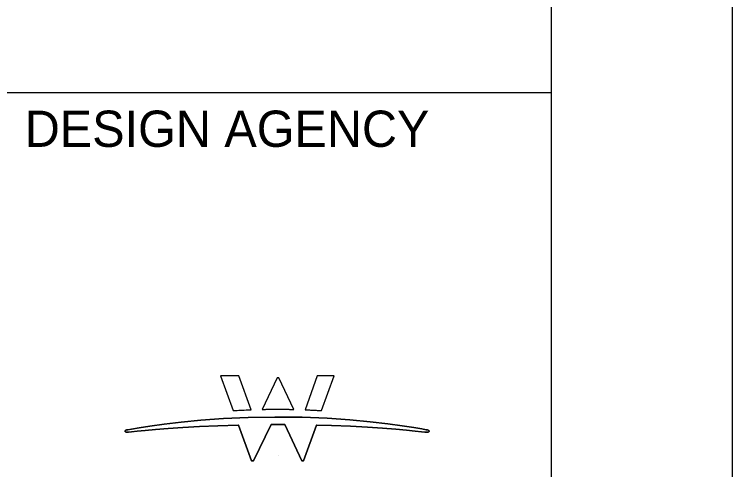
# Model space of a CAD drawing. Extents: x 0 to 34, y 0 to 22.
# Drawn here: x 32.021 to 34, y 3.46 to 4.716 of the extents above; entities that cross this region are included whole.
import ezdxf

# ---------------------------------------------------------------- set-up
doc = ezdxf.new("R2010")
doc.units = 0
for name, color, linetype in [('SH_Border', 7, 'Continuous'), ('SH_Cut_Line', 7, 'Continuous'), ('SH_Data', 7, 'Continuous'), ('SH_Text', 7, 'Continuous')]:
    doc.layers.add(name, color=color, linetype=linetype)

msp = doc.modelspace()

# ---------------------------------------------------------------- linework, layer by layer
at = {"layer": 'SH_Border'}
msp.add_line((32, 4.5), (33.5, 4.5), dxfattribs=at)
msp.add_lwpolyline([(1.5, 21.5), (33.5, 21.5), (33.5, 0.5), (1.5, 0.5)], close=True, dxfattribs=at)
at = {"layer": 'SH_Cut_Line'}
msp.add_lwpolyline([(0, 0), (34, 0), (34, 22), (0, 22)], close=True, dxfattribs=at)
at = {"layer": 'SH_Data'}
msp.add_line((32.75, 3.5), (32.75, 3.5), dxfattribs=at)
at = {"layer": 'SH_Text'}
for points in [[(32.6397, 3.7186), (32.5891, 3.7186), (32.6242, 3.6226), (32.6302, 3.6229), (32.635, 3.6232), (32.6399, 3.6235), (32.6448, 3.6237), (32.6497, 3.624), (32.6547, 3.6242), (32.6597, 3.6244), (32.6647, 3.6246), (32.6697, 3.6248), (32.6736, 3.625)], [(32.7499, 3.713), (32.7451, 3.713), (32.7042, 3.6259), (32.7045, 3.6259), (32.7067, 3.6259), (32.7088, 3.6259), (32.711, 3.626), (32.7132, 3.626), (32.7154, 3.6261), (32.7175, 3.6261), (32.7197, 3.6261), (32.7219, 3.6261), (32.7241, 3.6262), (32.7263, 3.6262), (32.7285, 3.6262), (32.7307, 3.6262), (32.733, 3.6262), (32.7352, 3.6263), (32.7374, 3.6263), (32.7396, 3.6263), (32.7419, 3.6263), (32.7441, 3.6263), (32.7464, 3.6263), (32.7488, 3.6263), (32.7512, 3.6263), (32.7536, 3.6263), (32.7559, 3.6263), (32.7583, 3.6263), (32.7607, 3.6262), (32.7631, 3.6262), (32.7654, 3.6262), (32.7678, 3.6262), (32.7701, 3.6261), (32.7725, 3.6261), (32.7748, 3.6261), (32.7772, 3.6261), (32.7795, 3.626), (32.7818, 3.626), (32.7842, 3.6259), (32.7865, 3.6259), (32.7888, 3.6258), (32.7911, 3.6258), (32.7915, 3.6258)], [(32.8556, 3.7186), (32.822, 3.6248), (32.8232, 3.6248), (32.8255, 3.6247), (32.8279, 3.6246), (32.8302, 3.6245), (32.8325, 3.6244), (32.8348, 3.6243), (32.8371, 3.6242), (32.8394, 3.6241), (32.8417, 3.624), (32.844, 3.6239), (32.8463, 3.6238), (32.8486, 3.6237), (32.8508, 3.6236), (32.8531, 3.6234), (32.8554, 3.6233), (32.8576, 3.6232), (32.8598, 3.6231), (32.8621, 3.6229), (32.8643, 3.6228), (32.8676, 3.6226), (32.9022, 3.7186)]]:
    msp.add_lwpolyline(points, close=True, dxfattribs=at)
for points in [[(32.6397, 3.7186), (32.5891, 3.7186), (32.6242, 3.6226), (32.6302, 3.6229), (32.635, 3.6232), (32.6399, 3.6235), (32.6448, 3.6237), (32.6497, 3.624), (32.6547, 3.6242), (32.6597, 3.6244), (32.6647, 3.6246), (32.6697, 3.6248), (32.6736, 3.625), (32.6397, 3.7186)], [(32.7499, 3.713), (32.7451, 3.713), (32.7042, 3.6259), (32.7067, 3.6259), (32.7088, 3.6259), (32.711, 3.626), (32.7132, 3.626), (32.7154, 3.6261), (32.7175, 3.6261), (32.7197, 3.6261), (32.7219, 3.6261), (32.7241, 3.6262), (32.7263, 3.6262), (32.7285, 3.6262), (32.7307, 3.6262), (32.733, 3.6262), (32.7352, 3.6263), (32.7374, 3.6263), (32.7396, 3.6263), (32.7419, 3.6263), (32.7441, 3.6263), (32.7464, 3.6263), (32.7488, 3.6263), (32.7512, 3.6263), (32.7536, 3.6263), (32.7559, 3.6263), (32.7583, 3.6263), (32.7607, 3.6262), (32.7631, 3.6262), (32.7654, 3.6262), (32.7678, 3.6262), (32.7701, 3.6261), (32.7725, 3.6261), (32.7748, 3.6261), (32.7772, 3.6261), (32.7795, 3.626), (32.7818, 3.626), (32.7842, 3.6259), (32.7865, 3.6259), (32.7888, 3.6258), (32.7911, 3.6258), (32.7499, 3.713)], [(32.8556, 3.7186), (32.822, 3.6248), (32.8232, 3.6248), (32.8255, 3.6247), (32.8279, 3.6246), (32.8302, 3.6245), (32.8325, 3.6244), (32.8348, 3.6243), (32.8371, 3.6242), (32.8394, 3.6241), (32.8417, 3.624), (32.844, 3.6239), (32.8463, 3.6238), (32.8486, 3.6237), (32.8508, 3.6236), (32.8531, 3.6234), (32.8554, 3.6233), (32.8576, 3.6232), (32.8598, 3.6231), (32.8621, 3.6229), (32.8643, 3.6228), (32.8676, 3.6226), (32.9022, 3.7186), (32.8556, 3.7186)], [(32.6375, 3.5827), (32.5819, 3.5809), (32.531, 3.5786), (32.4852, 3.5759), (32.4448, 3.5731), (32.4101, 3.5703), (32.3816, 3.5677), (32.3595, 3.5655), (32.3442, 3.5638), (32.336, 3.5629), (32.3341, 3.5627), (32.3328, 3.5627), (32.3316, 3.5628), (32.3305, 3.563), (32.3294, 3.5632), (32.3285, 3.5636), (32.3277, 3.564), (32.327, 3.5644), (32.3265, 3.565), (32.3262, 3.5655), (32.3261, 3.5661), (32.3263, 3.5667), (32.3266, 3.5672), (32.3271, 3.5677), (32.3277, 3.5682), (32.3285, 3.5686), (32.3295, 3.5689), (32.3306, 3.5692), (32.3317, 3.5694), (32.3337, 3.5697), (32.3442, 3.5716), (32.3647, 3.5752), (32.3947, 3.58), (32.4336, 3.5854), (32.4807, 3.5909), (32.5354, 3.5962), (32.5971, 3.6006), (32.6652, 3.6037), (32.739, 3.6049), (32.8139, 3.6041), (32.883, 3.6013), (32.9457, 3.5971), (33.0015, 3.592), (33.0498, 3.5864), (33.0899, 3.581), (33.1214, 3.576), (33.1435, 3.5722), (33.1557, 3.5699), (33.1585, 3.5693), (33.1597, 3.5692), (33.1608, 3.5689), (33.1617, 3.5686), (33.1625, 3.5681), (33.1632, 3.5677), (33.1637, 3.5672), (33.164, 3.5667), (33.1641, 3.5661), (33.164, 3.5655), (33.1637, 3.565), (33.1633, 3.5645), (33.1628, 3.5641), (33.1621, 3.5637), (33.1613, 3.5634), (33.1605, 3.5631), (33.1595, 3.5629), (33.1585, 3.5628), (33.1574, 3.5627), (33.1566, 3.5627), (33.1565, 3.5627), (33.1563, 3.5627), (33.1562, 3.5627), (33.1561, 3.5627), (33.1559, 3.5627), (33.1558, 3.5627), (33.1556, 3.5627), (33.1555, 3.5627), (33.1553, 3.5627), (33.1525, 3.5631), (33.1425, 3.5642), (33.1255, 3.5661), (33.1018, 3.5685), (33.0718, 3.5711), (33.0358, 3.574), (32.9941, 3.5767), (32.9471, 3.5793), (32.895, 3.5815), (32.8549, 3.5827), (32.8549, 3.5827), (32.8547, 3.5827), (32.8545, 3.5827), (32.8542, 3.5827), (32.854, 3.5827), (32.8537, 3.5827), (32.8535, 3.5827), (32.8534, 3.5827), (32.8177, 3.4838), (32.8131, 3.4838), (32.7661, 3.584), (32.766, 3.584), (32.7658, 3.584), (32.7655, 3.584), (32.7652, 3.584), (32.7648, 3.584), (32.7645, 3.584), (32.7642, 3.584), (32.764, 3.584), (32.7638, 3.584), (32.7625, 3.584), (32.7606, 3.584), (32.7588, 3.5841), (32.757, 3.5841), (32.7553, 3.5841), (32.7536, 3.5841), (32.7518, 3.5841), (32.75, 3.5841), (32.7481, 3.5841), (32.7461, 3.5841), (32.7442, 3.5841), (32.7425, 3.5841), (32.7408, 3.5841), (32.7392, 3.5841), (32.7376, 3.5841), (32.736, 3.5841), (32.7343, 3.5841), (32.7326, 3.584), (32.7309, 3.584), (32.7301, 3.584), (32.73, 3.584), (32.7298, 3.584), (32.7296, 3.584), (32.7293, 3.584), (32.729, 3.584), (32.7287, 3.584), (32.7285, 3.584), (32.7284, 3.584), (32.7283, 3.584), (32.6797, 3.4838), (32.675, 3.4838), (32.6388, 3.5827), (32.6387, 3.5827), (32.6386, 3.5827), (32.6384, 3.5827), (32.6382, 3.5827), (32.638, 3.5827), (32.6378, 3.5827), (32.6376, 3.5827), (32.6375, 3.5827), (32.6375, 3.5827)], [(33.1566, 3.5627), (33.1574, 3.5627), (33.1585, 3.5628), (33.1595, 3.5629), (33.1605, 3.5631), (33.1613, 3.5634), (33.1621, 3.5637), (33.1628, 3.5641), (33.1633, 3.5645), (33.1637, 3.565), (33.164, 3.5655), (33.1641, 3.5661), (33.164, 3.5667), (33.1637, 3.5672), (33.1632, 3.5677), (33.1625, 3.5681), (33.1617, 3.5686), (33.1608, 3.5689), (33.1597, 3.5692), (33.1585, 3.5693), (33.1557, 3.5699), (33.1435, 3.5722), (33.1214, 3.576), (33.0899, 3.581), (33.0498, 3.5864), (33.0015, 3.592), (32.9457, 3.5971), (32.883, 3.6013), (32.8139, 3.6041), (32.739, 3.6049), (32.6652, 3.6037), (32.5971, 3.6006), (32.5354, 3.5962), (32.4807, 3.5909), (32.4336, 3.5854), (32.3947, 3.58), (32.3647, 3.5752), (32.3442, 3.5716), (32.3337, 3.5697), (32.3317, 3.5694), (32.3306, 3.5692), (32.3295, 3.5689), (32.3285, 3.5686), (32.3277, 3.5682), (32.3271, 3.5677), (32.3266, 3.5672), (32.3263, 3.5667), (32.3261, 3.5661), (32.3262, 3.5655), (32.3265, 3.565), (32.327, 3.5644), (32.3277, 3.564), (32.3285, 3.5636), (32.3294, 3.5632), (32.3305, 3.563), (32.3316, 3.5628), (32.3328, 3.5627), (32.3341, 3.5627), (32.336, 3.5629), (32.3442, 3.5638), (32.3595, 3.5655), (32.3816, 3.5677), (32.4101, 3.5703), (32.4448, 3.5731), (32.4852, 3.5759), (32.531, 3.5786), (32.5819, 3.5809), (32.6375, 3.5827), (32.6384, 3.5827)], [(32.6384, 3.5827), (32.6388, 3.5827)], [(32.6388, 3.5827), (32.675, 3.4838), (32.6797, 3.4838), (32.7285, 3.584), (32.729, 3.584), (32.7296, 3.584), (32.7301, 3.584), (32.7309, 3.584), (32.7326, 3.584), (32.7343, 3.5841), (32.736, 3.5841), (32.7376, 3.5841), (32.7392, 3.5841), (32.7408, 3.5841), (32.7425, 3.5841), (32.7442, 3.5841), (32.7461, 3.5841), (32.7481, 3.5841), (32.75, 3.5841), (32.7518, 3.5841), (32.7536, 3.5841), (32.7553, 3.5841), (32.757, 3.5841), (32.7588, 3.5841), (32.7606, 3.584), (32.7625, 3.584), (32.7642, 3.584), (32.7648, 3.584), (32.7655, 3.584), (32.7661, 3.584), (32.8131, 3.4838), (32.8177, 3.4838), (32.8537, 3.5827), (32.8542, 3.5827), (32.8549, 3.5827)], [(32.8549, 3.5827), (32.8549, 3.5827)], [(32.8549, 3.5827), (32.895, 3.5815), (32.9471, 3.5793), (32.9941, 3.5767), (33.0358, 3.574), (33.0718, 3.5711), (33.1018, 3.5685), (33.1255, 3.5661), (33.1425, 3.5642), (33.1525, 3.5631), (33.1556, 3.5627), (33.1561, 3.5627), (33.1565, 3.5627)], [(33.1565, 3.5627), (33.1566, 3.5627)]]:
    msp.add_lwpolyline(points, dxfattribs=at)

# ---------------------------------------------------------------- texts
at = {"layer": 'SH_Data'}
msp.add_text('DESIGN AGENCY', height=0.1, dxfattribs=at).set_placement((32.05, 4.35))

doc.saveas('drawing.dxf')
